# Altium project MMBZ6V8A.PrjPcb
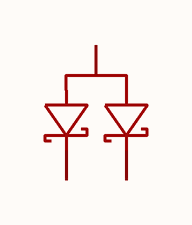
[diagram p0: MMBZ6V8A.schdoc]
1 sheet, 1 parts. Net scope: global (net labels, ports and power ports of the same name join across sheets).

## Sheet MMBZ6V8A.schdoc
size 127 x 101 mm

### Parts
U?  mmbz6v8a  [SOT-23-3_L2.9-W1.3-P1.90-LS2.4-BR]  (value not drawn)

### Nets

Not connected (* = marked no-connect by the designer): U? 1 2 3

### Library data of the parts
U? = mmbz6v8a: 极性:单向;反向截止电压(Vrwm):4.5V;钳位电压:9.6V;峰值脉冲电流(Ipp):2.5A;峰值脉冲功率(Ppp):24W;击穿电压(VBR):6.46V;; Manufacturer: JSMSEMI(杰盛微); AddInBom: yes; ModelId: c62791f0466c4ae2a892c056b845b0ca; ModelName: SOT-23-3P_L2.9-W1.3-H1.0-LS2.4-P0.95; ModelTransform: 98.425,114.173,0,180,0,0,0.0005,-0.0005,0; Polarity: 单向; Reverse Stand-Off Voltage (Vrwm): 4.5V; Clamping Voltage: 9.6V; Peak Pulse Current (Ipp): 2.5A; Peak Pulse Power Dissipation (Ppp): 24W; Voltage - Breakdown: 6.46V; Reverse Leakage Current (Ir): 500nA; Number of Channels: 双路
